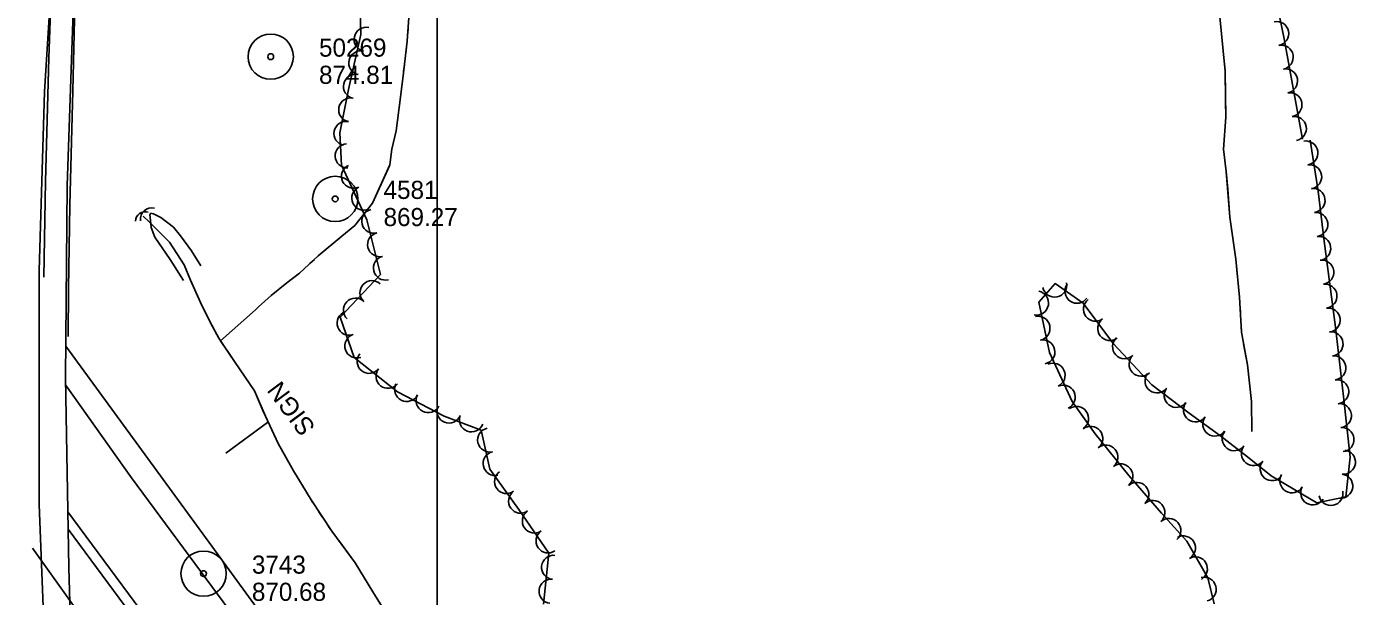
# Model space of a CAD drawing. Extents: x 353423 to 364002, y 127000 to 201942.
# Drawn here: x 361364.1 to 361803.9, y 129775.8 to 129964.5 of the extents above; entities that cross this region are included whole.
import ezdxf

# ---------------------------------------------------------------- set-up
doc = ezdxf.new("R2010")
doc.units = 0
for name, color, linetype in [('E_DTM_SlopeBottom', 7, 'Continuous'), ('E_DTM_SlopeTop', 7, 'Continuous'), ('E_FEN_Generic', 7, 'Continuous'), ('E_LAND_BrushLine', 7, 'Continuous'), ('E_LAND_TreeLine', 7, 'Continuous'), ('E_MISCPROP', 7, 'Continuous'), ('E_RDWY_AsphConc', 7, 'Continuous'), ('E_STRUCT_WingWall', 7, 'Continuous')]:
    doc.layers.add(name, color=color, linetype=linetype)

msp = doc.modelspace()

# ---------------------------------------------------------------- linework, layer by layer
at = {"layer": 'E_DTM_SlopeBottom'}
for points in [[(361394.46, 129527.22), (361371.9, 129556.48), (361345.29, 129590.29), (361338.69, 129663.33), (361334.92, 129733.14), (361332.72, 129812.42), (361332.84, 129898.36), (361336.44, 129995.72), (361338.07, 130031.71), (361379.67, 129975.96), (361377.53, 129911.84), (361376.95, 129848.18), (361378.05, 129785.39), (361379.39, 129738.81), (361383.8, 129663.52), (361388.81, 129597.64), (361392.53, 129549.2), (361394.46, 129527.22)], [(361334.58, 129869.07), (361335.8, 129935.63), (361336.7, 129972.19), (361337.9, 130020.86), (361337.99, 130028.55), (361340.14, 130028.39), (361379, 129976.63), (361380.15, 129976.55), (361379.33, 129943.21), (361378.42, 129905.32), (361377.93, 129877.69), (361377.77, 129861.83)]]:
    msp.add_lwpolyline(points, dxfattribs=at)
msp.add_arc((361403.33, 129899.94), 3.24, 71.9782, 178.2177, dxfattribs=at)
msp.add_ellipse((361405.73, 129900.39), major_axis=(-2.77, 3.13), ratio=0.92522, start_param=5.356056, end_param=7.210287, dxfattribs=at)
at = {"layer": 'E_DTM_SlopeTop'}
for points in [[(361426.93, 129275.43), (361406.67, 129382.34), (361399.91, 129426.18), (361386.19, 129536.68), (361379.38, 129605.97), (361373.1, 129682.38), (361368.21, 129806.26), (361368.26, 129883.74), (361370.04, 129942.87), (361372.6, 129985.44), (361376.57, 130111.1), (361379.51, 130207.61), (361382.13, 130287.18), (361384.45, 130367.85), (361387.51, 130458.43), (361390, 130547.51), (361392.28, 130623.35), (361395.89, 130724.33), (361398.26, 130804.64), (361402.32, 130935.65), (361404.44, 130996.4), (361408.08, 131120.47), (361409.99, 131176.04)], [(361369.72, 129881.48), (361370.32, 129913.19), (361371.41, 129954.04), (361372.54, 129985.22)], [(361747.63, 129312.82), (361722.73, 129354.6), (361675.67, 129431.31), (361612.87, 129530.01), (361563.16, 129603.02), (361428.37, 129788.37), (361377.05, 129858.7)], [(361376.99, 129845.82), (361398.83, 129815.11), (361455.73, 129738.06), (361501.71, 129675.72), (361555.45, 129599.93), (361606.25, 129526.41), (361647.01, 129462.73), (361678.24, 129413.04), (361713.86, 129354.01), (361741.1, 129307.24)], [(361377.73, 129803.8), (361449.85, 129706.27), (361507.31, 129627.44), (361568.26, 129539.47), (361612.64, 129472.81), (361654.35, 129407.07), (361695.66, 129338.64), (361718.63, 129298.31)], [(361716.88, 129295.15), (361688.27, 129344.46), (361646.61, 129412.9), (361623.66, 129449), (361583.63, 129510.64), (361533.98, 129583.65), (361486.88, 129649.85), (361454.76, 129693.3), (361400.3, 129767.57), (361377.83, 129798.04)]]:
    msp.add_lwpolyline(points, dxfattribs=at)
at = {"layer": 'E_FEN_Generic'}
for points in [[(361486.36, 130097), (361484.98, 130085.61), (361479.81, 130060.74), (361473.92, 130038.03), (361467.25, 130018.28), (361468.78, 130000.68), (361474.07, 129983.57), (361474.67, 129961.92), (361470.55, 129943.68), (361467.68, 129929.26), (361468.27, 129918.58), (361476.7, 129900.53), (361481.21, 129882.42), (361467.88, 129868.31), (361472.5, 129854.9), (361486.77, 129843.59), (361502.3, 129835.53), (361514.46, 129830.81), (361517.43, 129817.95), (361527.01, 129804.54), (361536.89, 129790.17), (361535.09, 129773.21)], [(361786.39, 129927.17), (361780.3, 129960.43), (361772.05, 130000.68)], [(361757.13, 129773.38), (361754.99, 129781.94), (361748.03, 129794.11), (361739.73, 129803.42), (361728.84, 129815.79), (361717.69, 129829.67), (361710.14, 129840.31), (361702.59, 129856.54), (361699.11, 129873.2), (361704.43, 129879.4), (361713.77, 129872.86), (361723.74, 129859.41), (361736.47, 129845.9), (361748.83, 129836.52), (361758.88, 129829.15), (361768.17, 129821.97), (361775.92, 129815.75), (361791.12, 129806.84), (361800.72, 129808.79), (361802.15, 129821.91), (361799.96, 129842.02), (361797.22, 129864.91), (361793.49, 129893.42), (361791.56, 129910.01), (361788.89, 129926.89)]]:
    msp.add_lwpolyline(points, dxfattribs=at)
for centre, radius, start, end in [((361777.8, 129962.19), 4, 281.5916, 101.5763), ((361476.44, 129960.27), 3.99, 77.2831, 257.2678), ((361779.28, 129954.36), 4, 280.3944, 100.379), ((361474.68, 129952.48), 3.99, 77.2831, 257.2678), ((361472.92, 129944.7), 3.99, 77.2831, 257.2678), ((361780.72, 129946.49), 4, 280.3944, 100.379), ((361471.34, 129936.93), 3.99, 78.7527, 258.7374), ((361782.17, 129938.61), 4, 280.3944, 100.379), ((361469.78, 129929.11), 3.99, 78.7527, 258.7374), ((361783.61, 129930.73), 4, 280.3944, 100.379), ((361787.45, 129922.62), 3.99, 278.9975, 98.9822), ((361470.19, 129921.67), 3.99, 93.1917, 273.1763), ((361472.28, 129914.93), 3.99, 115.0428, 295.0275), ((361788.7, 129914.74), 3.99, 278.9975, 98.9822), ((361475.66, 129907.7), 3.99, 115.0428, 295.0275), ((361789.82, 129906.93), 3.99, 276.6456, 96.6302), ((361478.98, 129900.03), 3.99, 103.9784, 283.9631), ((361790.74, 129899), 3.99, 276.6456, 96.6302), ((361480.9, 129892.28), 3.99, 103.9784, 283.9631), ((361791.69, 129891.05), 3.99, 277.4691, 97.4538), ((361482.83, 129884.54), 3.99, 103.9784, 283.9631), ((361792.73, 129883.14), 3.99, 277.4691, 97.4538), ((361478.39, 129876.39), 3.99, 46.6382, 226.6228), ((361704.34, 129878.89), 3.99, 190.9472, 10.9318), ((361711.69, 129876.86), 3.99, 144.9683, 324.953), ((361793.77, 129875.22), 3.99, 277.4691, 97.4538), ((361472.91, 129870.59), 3.99, 46.6382, 226.6228), ((361698.31, 129872.95), 3.99, 259.0578, 79.0425), ((361717.82, 129870.9), 3.99, 126.5874, 306.5721), ((361470.79, 129866.28), 3.99, 109.0368, 289.0215), ((361794.8, 129867.31), 3.99, 277.4691, 97.4538), ((361698.78, 129864.59), 3.99, 281.7968, 101.7815), ((361722.57, 129864.49), 3.99, 126.5874, 306.5721), ((361473.39, 129858.74), 3.99, 109.0368, 289.0215), ((361700.41, 129856.78), 3.99, 281.7968, 101.7815), ((361727.46, 129858.51), 3.99, 133.2899, 313.2746), ((361795.78, 129859.42), 3.99, 276.822, 96.8067), ((361477.44, 129853.65), 3.99, 141.5881, 321.5728), ((361732.93, 129852.71), 3.99, 133.2899, 313.2746), ((361703.78, 129849.04), 3.99, 294.9718, 114.9564), ((361796.72, 129851.49), 3.99, 276.822, 96.8067), ((361483.69, 129848.7), 3.99, 141.5881, 321.5728), ((361738.21, 129847.2), 3.99, 142.8158, 322.8004), ((361797.67, 129843.57), 3.99, 276.822, 96.8067), ((361489.85, 129844.34), 3.99, 152.6033, 332.588), ((361496.94, 129840.67), 3.99, 152.6033, 332.588), ((361707.14, 129841.81), 3.99, 294.9718, 114.9564), ((361744.56, 129842.38), 3.99, 142.8158, 322.8004), ((361503.85, 129837.17), 3.99, 158.7774, 338.7621), ((361711.54, 129834.73), 3.99, 305.3559, 125.3406), ((361750.9, 129837.59), 3.99, 143.7551, 323.7397), ((361798.55, 129835.66), 3.99, 276.2246, 96.2093), ((361511.29, 129834.28), 3.99, 158.7774, 338.7621), ((361757.34, 129832.87), 3.99, 143.7551, 323.7397), ((361517.34, 129827.61), 3.99, 103.0374, 283.0221), ((361716.25, 129828.14), 3.99, 308.767, 128.7517), ((361763.75, 129828.03), 3.99, 142.3227, 322.3074), ((361799.41, 129827.73), 3.99, 276.2246, 96.2093), ((361721.24, 129821.92), 3.99, 308.767, 128.7517), ((361770.08, 129823.12), 3.99, 141.248, 321.2327), ((361519.14, 129819.83), 3.99, 103.0374, 283.0221), ((361776.31, 129818.12), 3.99, 141.248, 321.2327), ((361799.87, 129820.25), 3.99, 263.7825, 83.7671), ((361522.93, 129813.85), 3.99, 125.5397, 305.5244), ((361726.24, 129815.69), 3.99, 308.767, 128.7517), ((361782.84, 129814.11), 3.99, 149.6224, 329.6071), ((361799, 129812.32), 3.99, 263.7825, 83.7671), ((361731.52, 129809.59), 3.99, 311.3829, 131.3676), ((361789.72, 129810.08), 3.99, 149.6224, 329.6071), ((361527.57, 129807.36), 3.99, 125.5397, 305.5244), ((361736.79, 129803.6), 3.99, 311.3829, 131.3676), ((361795.74, 129809.91), 3.99, 191.4805, 11.4652), ((361532.14, 129800.77), 3.99, 124.5108, 304.4954), ((361742.1, 129797.62), 3.99, 311.7271, 131.7117), ((361536.66, 129794.19), 3.99, 124.5108, 304.4954), ((361746.92, 129791.85), 3.99, 299.7606, 119.7453), ((361538.49, 129785.44), 3.99, 83.9353, 263.92), ((361750.88, 129784.92), 3.99, 299.7606, 119.7453), ((361537.64, 129777.51), 3.99, 83.9353, 263.92), ((361753.78, 129778.18), 3.99, 284.0581, 104.0428)]:
    msp.add_arc(centre, radius, start, end, dxfattribs=at)
at = {"layer": 'E_LAND_BrushLine'}
msp.add_line((361443.77, 129833.39), (361430.03, 129823.22), dxfattribs=at)
at = {"layer": 'E_LAND_TreeLine'}
msp.add_line((361500, 129000), (361500, 131500), dxfattribs=at)
at = {"layer": 'E_MISCPROP'}
msp.add_lwpolyline([(361366.03, 129791.83), (361387.76, 129761.27), (361408.48, 129733.22), (361412.03, 129727.04), (361414.37, 129720.17), (361415.33, 129714.88), (361415.56, 129711.12), (361414.98, 129707.93), (361413.36, 129706.6), (361411.76, 129706.18), (361410.01, 129706.5), (361408.03, 129708), (361406.31, 129709.89), (361405.02, 129711.62), (361390.8, 129730.68), (361376.73, 129749.78), (361370.47, 129759.54)], dxfattribs=at)
at = {"layer": 'E_RDWY_AsphConc'}
for centre, radius in [((361444.85, 129954.53), 7.5), ((361444.85, 129954.53), 0.96), ((361466.21, 129907.42), 7.5), ((361466.21, 129907.42), 0.96), ((361422.63, 129783.34), 7.5), ((361422.63, 129783.34), 0.96)]:
    msp.add_circle(centre, radius, dxfattribs=at)
at = {"layer": 'E_STRUCT_WingWall'}
for points in [[(361756.95, 129991.24), (361758, 129982.08), (361758.88, 129968.83), (361759.54, 129962.06)], [(361490.72, 129969.08), (361490.01, 129959.65), (361488.79, 129949.14), (361487.79, 129941.17), (361486.43, 129929.95), (361484.93, 129923.94), (361484.29, 129918.69), (361478.55, 129905.98), (361472.72, 129898.67), (361468.43, 129895.07), (361460.59, 129888.58), (361454.35, 129882.87), (361450.14, 129879.62), (361445.04, 129875.48), (361440.83, 129871.7), (361439.78, 129870.69), (361428.29, 129860.45)], [(361758.88, 129968.83), (361760.73, 129949.76), (361760.94, 129934.48), (361760.17, 129923.93), (361761.11, 129916.49), (361762.34, 129901.34), (361764.27, 129887.44), (361765.49, 129874.85), (361766.13, 129863.31), (361768.16, 129852.48), (361769.45, 129840.3), (361769.62, 129830.38)], [(361490.31, 129963.67), (361490.16, 129961.67)], [(361489.78, 129957.68), (361489.55, 129955.68)], [(361759.93, 129958.04), (361760.13, 129956.03)], [(361489.08, 129951.7), (361488.85, 129949.71)], [(361760.52, 129952.01), (361760.71, 129950)], [(361488.36, 129945.73), (361487.79, 129941.17), (361486.43, 129929.95), (361484.93, 129923.94), (361484.29, 129918.69), (361483.59, 129917.12)], [(361760.79, 129945.96), (361760.81, 129943.94)], [(361760.87, 129939.9), (361760.94, 129934.48), (361760.17, 129923.93), (361761.11, 129916.49), (361761.58, 129910.71)], [(361483.59, 129917.12), (361478.55, 129905.98), (361472.72, 129898.67), (361468.43, 129895.07), (361466.99, 129893.88)], [(361761.58, 129910.71), (361762.34, 129901.34), (361764.27, 129887.44), (361764.83, 129881.6)], [(361402.65, 129901.71), (361404.69, 129899.76), (361411.35, 129893.07), (361416.18, 129885.59), (361418.36, 129880.56), (361421.63, 129873.14), (361424.97, 129866.42), (361427.73, 129861.28), (361433.1, 129853.27), (361439.48, 129843.92), (361443.08, 129835.54), (361447.34, 129826.44), (361452.41, 129817.44), (361458.23, 129807.74), (361465.05, 129797.43), (361472.86, 129786.91), (361478.6, 129777.36), (361485.83, 129765.85)], [(361402.65, 129901.71), (361404.69, 129899.76), (361411.35, 129893.07), (361416.18, 129885.59), (361418.36, 129880.56), (361418.87, 129879.4)], [(361405.19, 129902.71), (361404.88, 129902.12), (361404.94, 129901.39), (361405.32, 129897.98), (361406.5, 129894.71), (361411.57, 129887.39), (361416.03, 129880.36)], [(361405.19, 129902.71), (361404.88, 129902.12), (361404.94, 129901.39), (361405.32, 129897.98), (361406.5, 129894.71), (361411.57, 129887.39), (361416.03, 129880.36)], [(361405.19, 129902.71), (361406.01, 129902.51), (361408.54, 129901.3), (361412.68, 129898.1), (361414.99, 129895.18), (361418.64, 129890.28), (361421.78, 129885.27)], [(361405.19, 129902.71), (361406.01, 129902.51), (361408.54, 129901.3), (361412.68, 129898.1), (361414.99, 129895.18), (361418.64, 129890.28), (361421.78, 129885.27)], [(361463.9, 129891.32), (361462.36, 129890.05)], [(361459.32, 129887.42), (361457.84, 129886.07)], [(361454.89, 129883.35), (361454.35, 129882.87), (361453.34, 129882.08)], [(361450.16, 129879.63), (361450.14, 129879.62), (361445.04, 129875.48), (361440.83, 129871.7), (361439.78, 129870.69), (361428.29, 129860.45)], [(361420.42, 129875.87), (361421.2, 129874.11)], [(361765.23, 129877.58), (361765.42, 129875.57)], [(361422.87, 129870.64), (361423.73, 129868.92)], [(361765.68, 129871.54), (361765.79, 129869.52)], [(361425.47, 129865.48), (361426.38, 129863.79)], [(361766.01, 129865.48), (361766.12, 129863.46)], [(361428.29, 129860.45), (361433.1, 129853.27), (361439.48, 129843.92), (361442.62, 129836.6)], [(361766.85, 129859.49), (361768.16, 129852.48), (361769.45, 129840.3), (361769.62, 129830.38)], [(361442.62, 129836.6), (361443.08, 129835.54), (361447.34, 129826.44), (361452.41, 129817.44), (361455.69, 129811.97)], [(361457.67, 129808.66), (361458.23, 129807.74), (361458.7, 129807.03)], [(361460.82, 129803.82), (361461.88, 129802.21)], [(361464.01, 129799), (361465.05, 129797.43), (361465.07, 129797.4)], [(361467.37, 129794.31), (361472.86, 129786.91), (361478.6, 129777.36), (361482.62, 129770.96)]]:
    msp.add_lwpolyline(points, dxfattribs=at)

# ---------------------------------------------------------------- texts
at = {"layer": 'E_LAND_BrushLine'}
msp.add_text('SIGN', height=6, rotation=126.7563, dxfattribs=at).set_placement((361459.89, 129831.89))
at = {"layer": 'E_RDWY_AsphConc'}
for s, p in [('50269', (361460.85, 129954.53)), ('874.81', (361460.85, 129945.53)), ('4581', (361482.21, 129907.42)), ('869.27', (361482.21, 129898.42)), ('3743', (361438.63, 129783.34)), ('870.68', (361438.63, 129774.34))]:
    msp.add_text(s, height=6, dxfattribs=at).set_placement(p)

doc.saveas('drawing.dxf')
